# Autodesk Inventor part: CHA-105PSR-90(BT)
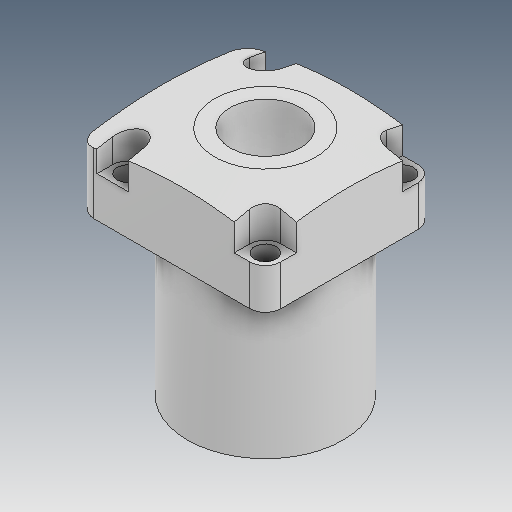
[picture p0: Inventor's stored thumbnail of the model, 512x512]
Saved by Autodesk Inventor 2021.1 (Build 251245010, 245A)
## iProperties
Created: 2021-05
Part Number: CHA-105PSR-90(BT)
Material: Ogólny
Document SubType Name: Modeling
Designer: user
Density: 1 g/cm^3
Appearance: Domyślna
Author: user
Revision Number: ÈÎºÎ
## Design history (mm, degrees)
feature "ÇÐ³ý-À­Éì4"
node "Bryła1"
